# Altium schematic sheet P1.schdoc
size 297 x 209 mm; Symbol: Drawing-Symbol_A4; Company: 嘉立创EDA; Version: V1.0; Page Size: A4; @Project Name: 极客营; @Update Date: 2026-02-20; @Create Date: 2026-02-20; Device: Drawing-Symbol_A4; @Board Name: Board1; @Page Name: P1; @Create Time: 10:59:29; @Page Count: 1; @Page No: 1; @Schematic Name: Schematic1; @Update Time: 10:59:29; @Assembly Variant: Basic; Border: 1; Title Block Position: 3; Size: A4; Width: 1170; Height: 825; Region Start: 1; X Region Count: 6; Y Region Count: 4; Blade Width: 10; Title Block: 1
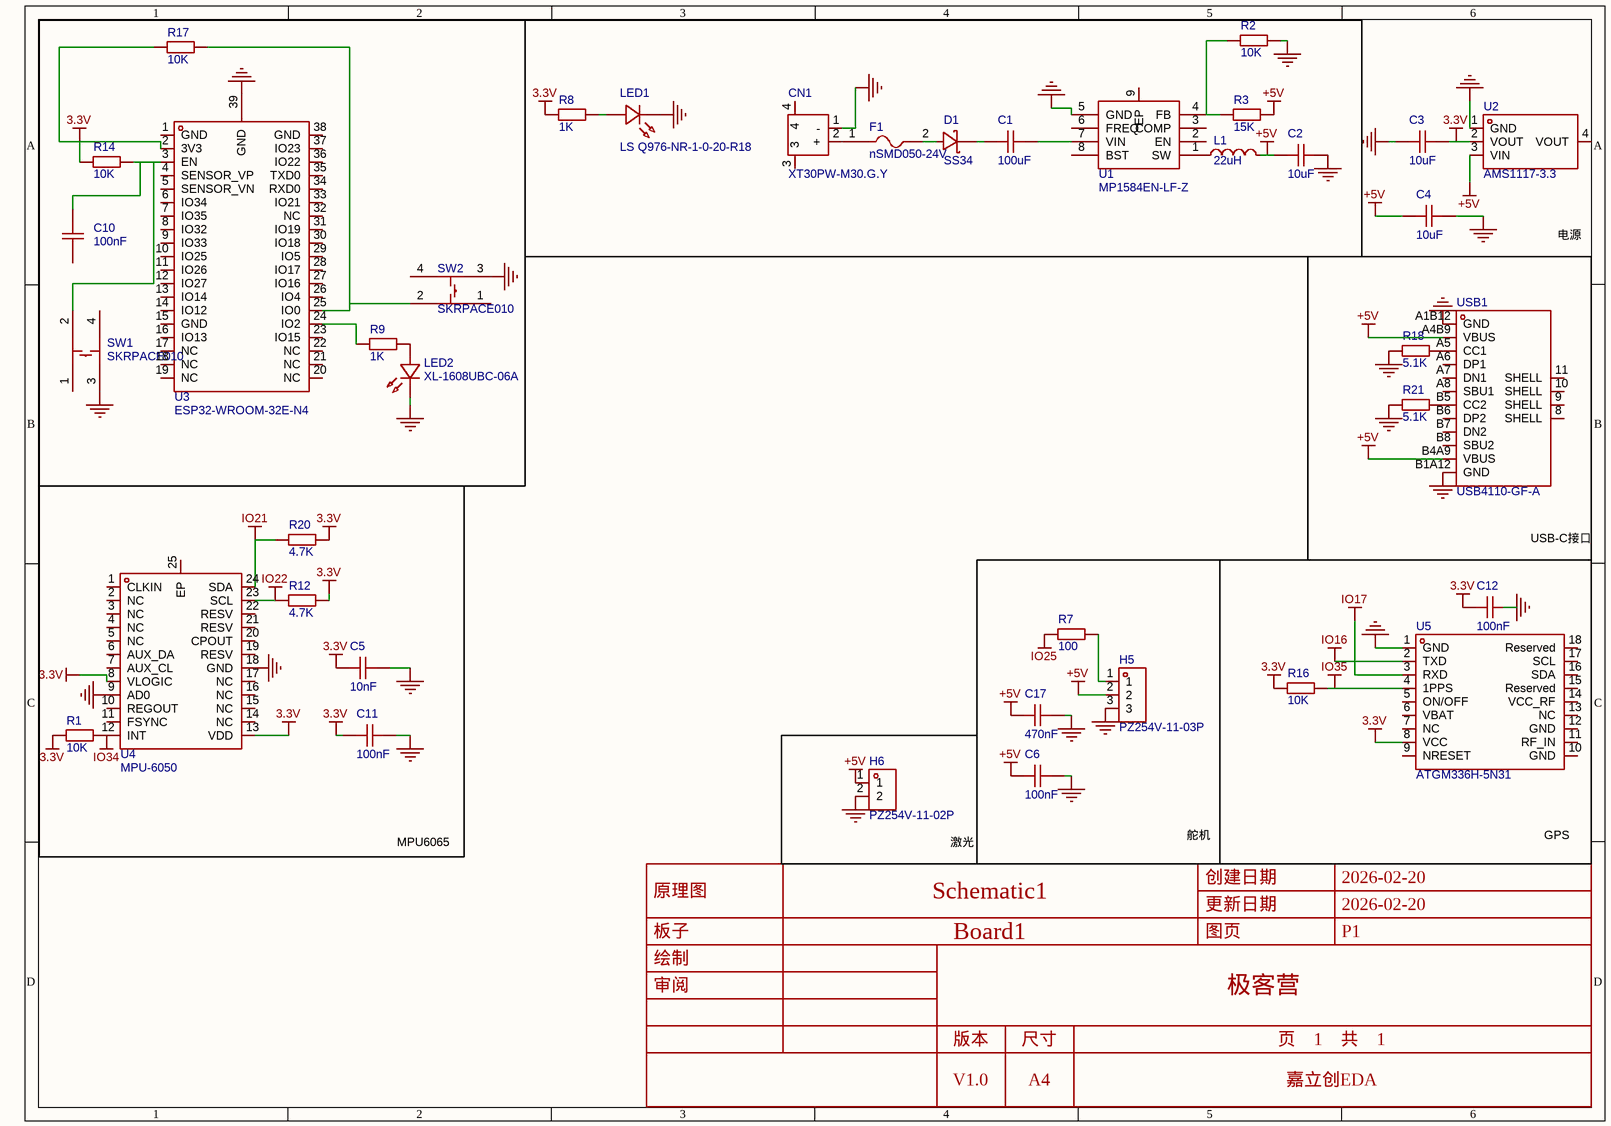
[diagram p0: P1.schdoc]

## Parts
C1  100uF  [C0603]
C2  10uF  [C0603]
C3  10uF  [C0603]
C4  10uF  [C0603]
C5  10nF  [C0603]
C6  100nF  [C0603]
C10  100nF  [C0603]
C11  100nF  [C0603]
C12  100nF  [C0603]
C17  470nF  [C0603]
CN1  XT30PW-M30.G.Y  [CONN-TH_XT30PW-M]
D1  SS34  [SMC_L6.9-W5.9-LS7.9-RD]
F1  nSMD050-24V  [F1206]
H5  PZ254V-11-03P  [HDR-TH_3P-P2.54-V-M_PZ254V-11-03P]
H6  PZ254V-11-02P  [HDR-TH_2P-P2.54-V-M]
L1  22uH  [L0603]
LED1  LS Q976-NR-1-0-20-R18  [LED0603-RD_RED]
LED2  XL-1608UBC-06A  [LED0603-R-RD]
R1  10K  [R0603]
R2  10K  [R0603]
R3  15K  [R0603]
R7  100  [R0603]
R8  1K  [R0603]
R9  1K  [R0603]
R12  4.7K  [R0603]
R14  10K  [R0603]
R16  10K  [R0603]
R17  10K  [R0603]
R18  5.1K  [R0603]
R20  4.7K  [R0603]
R21  5.1K  [R0603]
SW1  SKRPACE010  [KEY-SMD_4P-L4.2-W3.2-P2.20-LS4.6]
SW2  SKRPACE010  [KEY-SMD_4P-L4.2-W3.2-P2.20-LS4.6]
U1  MP1584EN-LF-Z  [SOIC-8_L5.0-W4.0-P1.27-LS6.0-BL-EP2.0]
U2  AMS1117-3.3  [SOT-223-3_L6.5-W3.4-P2.30-LS7.0-BR]
U3  ESP32-WROOM-32E-N4  [WIFI-SMD_ESP32-WROOM-32E]
U4  MPU-6050  [QFN-24_L4.0-W4.0-P0.50-BL-EP2.7]
U5  ATGM336H-5N31  [GPSM-SMD_ATGM336H-TR]
USB1  USB4110-GF-A  [USB-C-SMD_TYPE-C-16P-USB4110-GF-A]

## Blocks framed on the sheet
MPU6065: C5 C11 R1 R12 R20 U4
舵机: C6 C17 H5 R7
激光: H6

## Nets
3.3V: C3.2 C5.1 C11.1 C12.1 R1.2 R8.1 R12.1 R14.1 R16.1 R17.1 R20.1 U2.2(VOUT) U3.2(3V3) U4.8(VLOGIC) U4.13(VDD) U5.8(VCC)
+5V: C2.1 C4.1 C6.1 C17.1 H5.2 H6.1 L1.2 R3.2 U2.3(VIN) USB1.A4B9(VBUS) USB1.B4A9(VBUS)
GND: C2.2 C3.1 C4.2 C5.2 C6.2 C11.2 C12.2 C17.2 CN1.1(-) H5.3 H6.2 LED1.1(K) LED2.2(K) R2.2 R18.1 R21.1 SW1.3 SW2.3 U1.5(GND) U2.1(GND) U3.39(GND) U4.9(AD0) U4.18(GND) U5.1(GND) USB1.A1B12(GND) USB1.B1A12(GND)
IO16: U5.2(TXD)
IO17: U5.3(RXD)
IO21: R20.2 U4.24(SDA)
IO22: R12.2 U4.23(SCL)
IO25: R7.2
IO34: R1.1 U4.12(INT)
IO35: R16.2 U5.4(1PPS)
NetC1_1: C1.1 D1.1(C)
NetC1_2: C1.2 U1.7(VIN)
NetC10_1: C10.1 R14.2 SW1.2 U3.3(EN)
NetCN1_2: CN1.2(+) F1.1
NetD1_2: D1.2(A) F1.2
NetH5_1: H5.1 R7.1
NetL1_1: L1.1 U1.1(SW)
NetLED1_2: LED1.2(A) R8.2
NetLED2_1: LED2.1(A) R9.1
NetR2_1: R2.1 R3.1 U1.4(FB)
NetR9_2: R9.2 U3.24(IO2)
NetR17_2: R17.2 SW2.2 U3.25(IO0)
NetR18_2: R18.2 USB1.A5(CC1)
NetR21_2: R21.2 USB1.B5(CC2)

Not connected (* = marked no-connect by the designer): C10 2; CN1 3 4; SW1 1 4; SW2 1 4; U1 2(EN) 3(COMP) 6(FREQ) 8(BST) 9(EP); U2 4(VOUT); U3 1(GND) 4(SENSOR_VP) 5(SENSOR_VN) 6(IO34) 7(IO35) 8(IO32) 9(IO33) 10(IO25) 11(IO26) 12(IO27) 13(IO14) 14(IO12) 15(GND) 16(IO13) 17(NC) 18(NC) 19(NC) 20(NC) 21(NC) 22(NC) 23(IO15) 26(IO4) 27(IO16) 28(IO17) 29(IO5) 30(IO18) 31(IO19) 32(NC) 33(IO21) 34(RXD0) 35(TXD0) 36(IO22) 37(IO23) 38(GND); U4 1(CLKIN) 2(NC) 3(NC) 4(NC) 5(NC) 6(AUX_DA) 7(AUX_CL) 10(REGOUT) 11(FSYNC) 14(NC) 15(NC) 16(NC) 17(NC) 19(RESV) 20(CPOUT) 21(RESV) 22(RESV) 25(EP); U5 5(ON/OFF) 6(VBAT) 7(NC) 9(NRESET) 10(GND) 11(RF_IN) 12(GND) 13(NC) 14(VCC_RF) 15(Reserved) 16(SDA) 17(SCL) 18(Reserved); USB1 8(SHELL) 9(SHELL) 10(SHELL) 11(SHELL) A6(DP1) A7(DN1) A8(SBU1) B6(DP2) B7(DN2) B8(SBU2)

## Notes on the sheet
- 电源
- USB-C接口
- GPS

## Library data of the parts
C1 C5 C6 C10-C12 C17 = CAP_0603: Symbol: Capacitance; ConvertToPcb: yes; ModelId: ac125912035d415993ca9572d50418b10819f05c4eef4c71ace90d822a990e87; ModelName: C0603_L1.6-W0.8-H0.8; ModelTransform: 62.992,31.496,0,0,0,0,0,0,0
C2 C4 = CL10A106MA8NRNC: 容值:10uF;精度:±20%;额定电压:25V;温度系数:X5R;; Manufacturer: SAMSUNG(三星); Add into BOM: yes; 3D Model: ac125912035d415993ca9572d50418b1; 3D Model Transform: 62.992,31.496,0,0,0,0,0,0,0; Tolerance: ±20%; Voltage Rating: 25V; Temperature Coefficient: X5R; ModelName: C0603_L1.6-W0.8-H0.8
C3 = CL10A106KP8NNNC: 容值:10uF;精度:±10%;额定电压:10V;温度系数:X5R;; Manufacturer: SAMSUNG(三星); Add into BOM: yes; 3D Model: ac125912035d415993ca9572d50418b1; 3D Model Transform: 62.992,31.496,0,0,0,0,0,0,0; Tolerance: ±10%; Voltage Rating: 10V; Temperature Coefficient: X5R; ModelName: C0603_L1.6-W0.8-H0.8
CN1 = XT30PW-M30.G.Y: 类别:-;类型1:-;; Manufacturer: AMASS(艾迈斯); AddInBom: yes; ModelId: 722652c2597f41cd937322584dc4b29b0819f05c4eef4c71ace90d822a990e87; ModelTransform: 523.621,549.2115,0,0,0,0,-0.005,-39.568,-78.74; RatedVoltage: DC 500V; InterfaceType: 公头; RatedCurrent: 15A; RecommendedWireGauge: 16/18/20AWG; contact resistance: 1.2mΩ; specifications: 2pin
D1 = SS34_C154551: 正向压降(Vf):500mV@3A;直流反向耐压(Vr):40V;整流电流:3A;; Manufacturer: onsemi(安森美); AddInBom: yes; ModelId: 181deed3e51b4528a83dd624c23bafda0819f05c4eef4c71ace90d822a990e87; ModelTransform: 314.96,236.22,0,0,0,0,0,0,0; Voltage - DC Reverse(Vr): 40V; Current - Rectified: 3A; Reverse Leakage Current (Ir): 500uA@40V; Operating Junction Temperature Range: -55℃~+150℃; Non-Repetitive Peak Forward Surge Current: 100A
F1 = nSMD050-24V: 耐压(Vmax):24V;最大电流(Imax):100A;保持电流(Ihold):500mA;跳闸电流(Itrip):1A;; Manufacturer: 台湾陆海; AddInBom: yes; ModelId: f1628daad26847a79b887277a2bc85410819f05c4eef4c71ace90d822a990e87; ModelName: F1206_L3.2-W1.7-H0.6; ModelTransform: 125.984,66.929,0,0,0,0,0,0,0; Voltage - Max: 24V; Current - Max: 100A; Hold Current: 500mA; Trip Current: 1A; Power Dissipation: 600mW; Resistance - Initial (Ri) (Min): 150mΩ; Resistance - Post Trip (R1) (Max): 700mΩ; Time to Trip(Max): 100ms
H5 = PZ254V-11-03P: 插针结构:1x3P;间距:2.54mm;行距:-;圆针/方针:方针;安装方式:直插;排数:单排;总PIN位数:3P;额定电流:3A;额定电压:250V;配合针长度:6mm;塑高:2.5mm;端接针长度:3mm;工作温度:-40℃~+105℃;颜色:黑色;; Manufacturer: XFCN(兴飞); Symbol: PZ254V-11-03P_C2937625; AddInBom: yes; ModelId: bd28a638fbd247be9398fd5d39c366ec0819f05c4eef4c71ace90d822a990e87; ModelTransform: 300.3931,100,0,0,0,0,0,0,-118.11; Pin Structure: 1x3P; Pitch: 2.54mm; Circluar Pins/Square Pins: 方针; Current Rating: 3A; Voltage Rating (Max): 250V
H6 = PZ254V-11-02P: 插针结构:1x2P;间距:2.54mm;行距:-;圆针/方针:方针;安装方式:直插;排数:单排;总PIN位数:2P;额定电流:-;额定电压:-;配合针长度:6mm;塑高:2.5mm;端接针长度:3mm;触头材质:黄铜;触头镀层:-;工作温度:-40℃~+105℃;颜色:黑色;; Manufacturer: XFCN(兴飞); AddInBom: yes; ModelId: e35305ec3aa84b66b849f914b715e73f0819f05c4eef4c71ace90d822a990e87; ModelName: HDR2.54-M-LI-1X2P; ModelTransform: 200,100,0,0,0,0,0,0,-118.11; Pin Structure: 1x2P; Pitch: 2.54mm; Circluar Pins/Square Pins: 方针
L1 = L_0603: Symbol: SDFL1608S100KTF; AddInBom: yes; ModelId: 2bc5ec593d464d6ba9807aec0b5673c20819f05c4eef4c71ace90d822a990e87; ModelName: L0603_L1.6-W0.8-H0.5_BEAD; ModelTransform: 62.992,31.496,0,180,0,0,0.094,0.629,0
LED1 = LS Q976-NR-1-0-20-R18: 发光颜色:红色;正向压降(Vf):2.5V;正向电流:20mA;波长:627nm~639nm;透镜颜色:雾状白色透镜;发光强度:180mcd;发光角度:160°;工作温度:-30℃~+85℃;; Manufacturer: OSRAM(欧司朗); AddInBom: yes; ModelId: 74041d3a270d435c8600a9ab9b7641c00819f05c4eef4c71ace90d822a990e87; ModelTransform: 63.7794,31.496,0,0,0,0,0,-0.002,0; Illumination Color: 红色; Voltage - Forward(Vf): 2.5V; Forward Current: 20mA; Peak Wavelength: 645nm; Lens Color: 雾状白色透镜; Luminous Intensity: 180mcd; Viewing Angle: 160°
LED2 = XL-1608UBC-06A: 灯头类型:-;发光颜色:蓝色;正向压降(Vf):2.6V~3V;功率:-;正向电流:5mA;波长:456nm~476nm;二极管配置:-;透镜颜色:无色透明透镜;色温:-;发光强度:-;发光角度:130°;载带方式:正贴;工作温度:-;; Manufacturer: XINGLIGHT(成兴光); AddInBom: yes; ModelId: 8d3b40c214c440ee9cb5435c7b23d3470819f05c4eef4c71ace90d822a990e87; ModelTransform: 63.7794,31.496,0,0,0,0,0,0,0; Illumination Color: 蓝色; Forward Current: 5mA; Lens Color: 无色透明透镜; Viewing Angle: 130°; Mounting Sytle: 正贴
R1-R3 R7-R9 R12 R14 R16-R18 R20 R21 = Res_0603: Symbol: 电阻; ConvertToPcb: yes; ModelId: fc143cca1e79419f9cd78b61e9279f080819f05c4eef4c71ace90d822a990e87; ModelTransform: 31.8897,63.7794,0,90,0,0,0,0,0
SW1 SW2 = SKRPACE010: 电路结构:单刀单掷;按钮形状:椭圆形按钮;安装方式:立贴;开关长度:4.2mm;开关宽度:3.2mm;开关高度:2.5mm;触点电流:50mA;额定电压:16V;带灯:-;工作寿命:-;; Manufacturer: ALPSALPINE(阿尔卑斯阿尔派); AddInBom: yes; ModelId: 38f4e5ae1c0a49d7a4c1f95a650cdbea0819f05c4eef4c71ace90d822a990e87; ModelName: KEY-SMD_4P-L4.2-W3.2-H2.5-LS4.6-P2.2; ModelTransform: 184.96971,125.984,0,0,0,0,0,-0.005,0; Circuit: 单刀单掷; Actuator Style: 椭圆形按钮; Switch Height: 2.5mm; Contact Current: 50mA; Voltage Rating: 16V
U1 = MP1584EN-LF-Z: 功能类型:降压型;工作电压:4.5V~28V;输出电压:800mV~25V;输出电流:3A;输出类型:可调;; Manufacturer: MPS(芯源); AddInBom: yes; ModelId: d3dfb165ce8644e793b750cd6f375e750819f05c4eef4c71ace90d822a990e87; ModelTransform: 192.913,236.22,0,0,0,0,0,0,0; Function: 降压型; Output Current: 3A; Frequency - Switching: 100kHz~1.5MHz; Synchronous Rectifier: 否; Number of Outputs: 1; Topology: 降压式; Quiescent Current: 100uA; Switch tube (built-in/external): 内置; Output Type: 可调
U2 = AMS1117-3.3_C6186: 输出类型:固定;工作电压:16V;输出电压:3.3V;输出电流:1A;电源纹波抑制比(PSRR):72dB@(120Hz);输出极性:正极;; Manufacturer: AMS; AddInBom: yes; ModelId: 925194bf9823436183a3e0b978a8d0760819f05c4eef4c71ace90d822a990e87; ModelName: SOT-223-4P_L6.5-W3.5-H1.6-LS7.0-P2.30; ModelTransform: 279.89794,255.905,0,180,0,0,-3.9385,-0.0005,0; Output Type: 固定; Voltage - Supply: 16V; Output Voltage: 3.3V; Output Current: 1A; Voltage Dropout: 1.1V@(800mA); standby current: 5mA; Noise: 0.003%Vout; Output Configuration: 正极; Number of Outputs: 1
U3 = ESP32-WROOM-32E-N4: ESP32-WROOM-32E 集成 ESP32-D0WD-V3 芯片，具有高的稳定性和安全性能。; Manufacturer: ESPRESSIF(乐鑫); Symbol: ESP32-WROOM-32E(4MB); AddInBom: yes; ModelId: 002cfca93c884bd0a0e44ace4f3b20410819f05c4eef4c71ace90d822a990e87; ModelName: WIFI-SMD_L25.5-W18.0-H3.1-ESP32-WROOM-32E; ModelTransform: 1003.935,708.66,0,180,0,0,-148.762,0,0
U4 = MPU-6050: 传感器类型:加速度计陀螺仪;; Manufacturer: TDK InvenSense(应美盛); Symbol: MPU-6050_C24112; AddInBom: yes; ModelId: 3147e748bde04e038f0f2a42301e48160819f05c4eef4c71ace90d822a990e87; ModelTransform: 158.267,158.267,0,0,0,0,0,0,0
U5 = ATGM336H-5N31: GNSS类型:BDS；GPS;接口类型:UART；I2C;灵敏度:-148dBm;水平位置精确度:2.5m;; Manufacturer: 杭州中科微; AddInBom: yes; ModelId: c140405b66b14880af7b940da3c9f5960819f05c4eef4c71ace90d822a990e87; ModelName: GPSM-SMD_L10.1-W9.7-H2.4-P1.1; ModelTransform: 382.6764,397.637,0,90,0,0,0,0,0; Voltage - Supply: 2.7V~3.6V; Current - Supply: 25mA@3.3V; Accuracy: 2.5m; Time To First Fix: 35s
USB1 = USB4110-GF-A: 连接器类型:Type-C;协议标准:USB 2.0;公母:母;安装方式:卧贴;端口数量:1;额定电流 - 电源:5A;工作温度:-40℃~+85℃;; Manufacturer: GCT; AddInBom: yes; Connector Type: Type-C; Protocol Standard: USB 2.0; Gender: 母; Number of Ports: 1; Current Rating-Power: 5A; Voltage Rating: 48V; Detection color: 黑色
